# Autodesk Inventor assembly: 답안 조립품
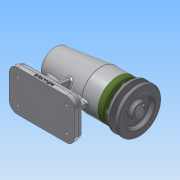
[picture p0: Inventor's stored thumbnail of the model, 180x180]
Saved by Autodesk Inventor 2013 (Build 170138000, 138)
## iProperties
Created: 2017-01
Part Number: 답안 조립품
Document SubType Name: Assembly
Designer: Administrator
Author: Administrator
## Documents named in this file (12)
- C:\Users\Administrator\Desktop\470108V1005\답안 조립품.iam
- C:\Users\Administrator\Desktop\470108V1005\V벨트풀리.ipt
- C:\Users\Administrator\Desktop\470108V1005\멈춤나사 M3x8.ipt
- C:\Users\Administrator\Desktop\470108V1005\베어링 6004.ipt
- C:\Users\Administrator\Desktop\470108V1005\베어링 51202.ipt
- C:\Users\Administrator\Desktop\470108V1005\본체.ipt
- C:\Users\Administrator\Desktop\470108V1005\볼트 M4 x 12.ipt
- C:\Users\Administrator\Desktop\470108V1005\어댑터슬리브.ipt
- C:\Users\Administrator\Desktop\470108V1005\오일 실.ipt
- C:\Users\Administrator\Desktop\470108V1005\축.ipt
- C:\Users\Administrator\Desktop\470108V1005\커버.ipt
- C:\Users\Administrator\Desktop\470108V1005\키 5 x 5 x 16.ipt
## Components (6 placed, 2 different names)
1. V벨트풀리:1
2. ISO 4762 M4 x 12:1
3. ISO 4762 M4 x 12:2
4. ISO 4762 M4 x 12:3
5. ISO 4762 M4 x 12:4
6. ISO 4762 M4 x 12:5
